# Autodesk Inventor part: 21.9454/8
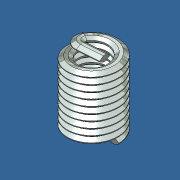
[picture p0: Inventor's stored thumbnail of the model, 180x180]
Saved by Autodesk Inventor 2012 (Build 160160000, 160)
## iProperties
Created: 2015-06
Part Number: 21.9454/8
Material: Stainless Steel
Document SubType Name: Modeling
Designer: Admin
Density: 7.75 g/cm^3
Description: M4X.7 HELICOIL 8mm LONG
Mass: 0.592377 g
Surface Area: 4.27276 cm^2
Volume: 0.0764357 cm^3
Vendor: S
Translation Standard: STEP AP203
FileName: 91732A776.step
PreProcessor: SolidWorks 2009
PostProcessor: Build: 160, Release: 2012 RTM - Date: Tue 03/01/2011
Sent Units: inch
Uncertainty: 1e-05
Author: Admin
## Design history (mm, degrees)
node "91732A7761"
node "NONE"
node "NONE_1"
node "Base1"
node "Base2"
